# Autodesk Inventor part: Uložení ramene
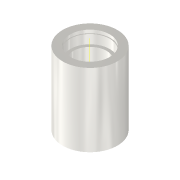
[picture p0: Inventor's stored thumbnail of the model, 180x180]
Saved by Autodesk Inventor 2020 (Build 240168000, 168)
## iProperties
Created: 2025-03
Part Number: Uložení ramene
Material: Ocel
Document SubType Name: Modeling
Designer: doma
Density: 7.85 g/cm^3
Appearance: Ocel
Mass: 3014.44 g
Surface Area: 604.934 cm^2
Volume: 384.005 cm^3
Author: doma
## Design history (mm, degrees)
sketch "Náčrt1"
  geometry: L1 (16.637, 5.951)-(16.637, 120.951); L2 (59.637, 96.62)-(59.637, 35.542); L3 (16.637, 5.951)-(33.637, 5.951); L4 (33.637, 5.951)-(33.637, 120.951); L5 (33.637, 120.951)-(16.637, 120.951); 1 further point
  constraints: 10 end point, 2 perpendicular, 2 vertical, 1 horizontal
  dimensions: "d0" = 115 distance of L1.start L1.end; "d1" = 43 distance between parallel lines of L2 L1; "d2" = 26 distance between parallel lines of L2 L4
revolve "Rotace1" sketch "Náčrt1" stored, may be unused: angle "d3" = 90 deg
node "Pracovní osa1"
sketch "Náčrt2"
  geometry: L1 (85.637, 5.951)-(33.637, 5.951) reference; L2 (85.637, 120.951)-(33.637, 120.951) reference; L3 (102.637, 5.951)-(16.637, 5.951) reference; L4 (33.637, 120.951)-(33.637, 5.951) reference; L5 (33.637, 27.951)-(33.637, 100.951); L6 (33.637, 27.951)-(28.637, 27.951); L7 (28.637, 27.951)-(28.637, 11.951); L8 (28.637, 11.951)-(27.137, 11.951); L9 (27.137, 11.951)-(27.137, 9.801); L10 (27.137, 9.801)-(28.637, 9.801); L11 (28.637, 9.801)-(28.637, 5.951); L12 (59.637, -24.19)-(59.637, 145.141) reference; L13 (102.637, 120.951)-(16.637, 120.951) reference; L14 (28.637, 120.951)-(28.637, 117.101); L15 (28.637, 117.101)-(27.137, 117.101); L16 (27.137, 117.101)-(27.137, 114.951); L17 (27.137, 114.951)-(28.637, 114.951); L18 (28.637, 114.951)-(28.637, 100.951); L19 (28.637, 100.951)-(33.637, 100.951); 1 further point
  constraints: 26 end point, 8 perpendicular, 8 point on line, 1 horizontal, 1 vertical
  dimensions: "d8" = 31 distance between parallel lines of L12 L11; "d9" = 32.5 distance between parallel lines of L12 L9; "d10" = 2.15 distance of L8.end L9.end; "d11" = 6 distance between parallel lines of L1 L8; "d12" = 16 distance of L6.end L7.end; "d13" = 2.15 distance of L15.end L16.end; "d14" = 31 distance between parallel lines of L12 L14; "d15" = 32.5 distance between parallel lines of L12 L16; "d20" = 14 distance of L17.end L18.end; "d21" = 6 distance between parallel lines of L13 L17
revolve "Rotace2" sketch "Náčrt2" stored, may be unused: angle "d18" = 90 deg
sketch "Náčrt3"
  geometry: 5 further points
  constraints: 4 other
  dimensions: "d25" = 360 deg dimension on point (0, 0) point (37.5, 0) (derived); "d34" = 37.5 distance of point (37.5, 0) point (0, 0)
hole "Díra1" sketch "Náčrt3" at (37.5, 0), (-18.75, 32.476), (-18.75, -32.476) diameter "d27" = 4.917; stored, may be unused: countersink angle "d31" = 90 deg, drill point angle "d33" = 118 deg; dims "d28" = 10, "d29" = 4, "d30" = 2, "d32" = 15.1
node "Těleso1"
